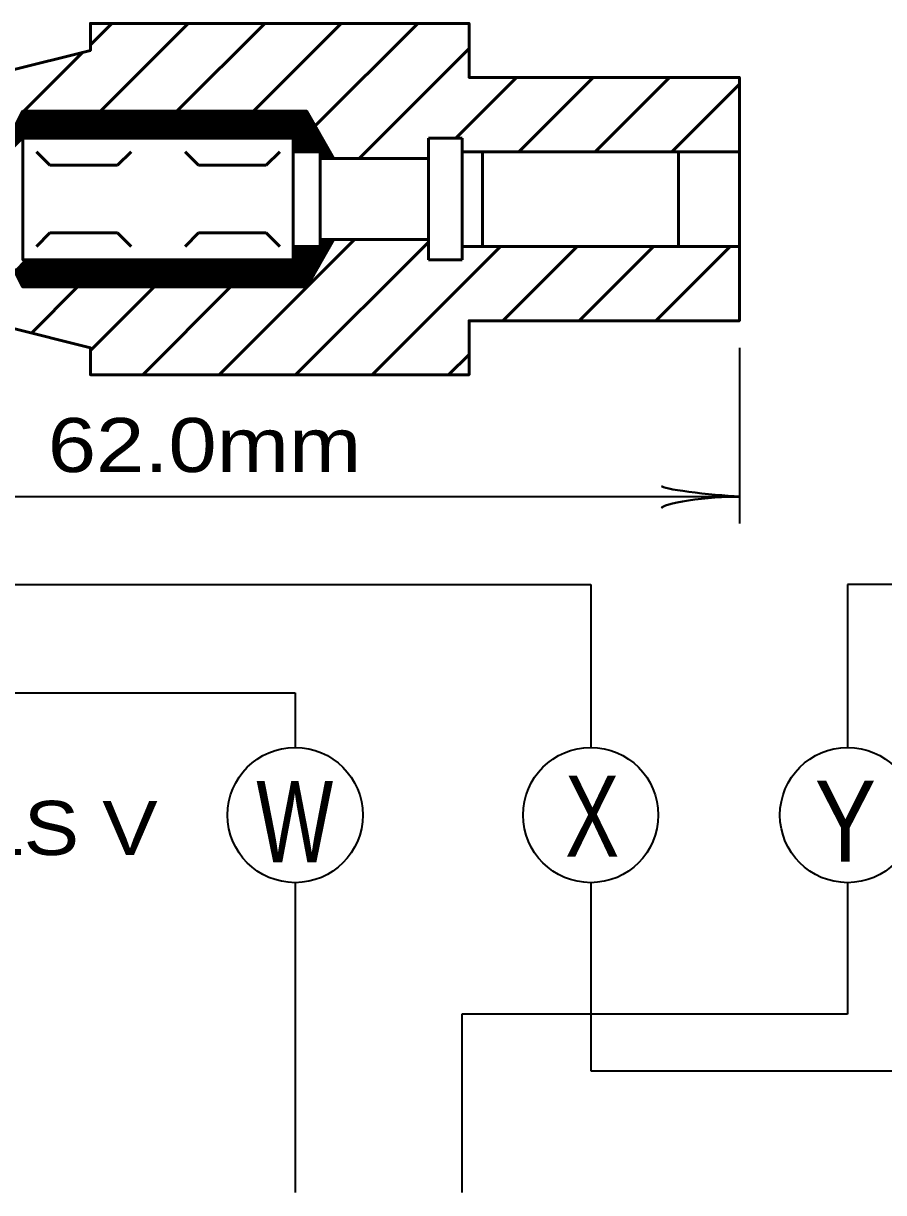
# Model space of a CAD drawing. Extents: x -32 to 824, y -6 to 538.
# Drawn here: x 382.7 to 420.9, y 130.6 to 182.5 of the extents above; entities that cross this region are included whole.
import ezdxf

# ---------------------------------------------------------------- set-up
doc = ezdxf.new("R2010")
doc.units = 0
doc.header["$LTSCALE"] = 1.1
doc.layers.add('1', color=7, linetype='Continuous', lineweight=53)

msp = doc.modelspace()

# ---------------------------------------------------------------- linework, layer by layer
at = {"layer": '1'}
for p, q in [((385.679, 181.513), (386.627, 182.462)), ((386.122, 178.562), (390.022, 182.462)), ((389.516, 178.562), (393.416, 182.462)), ((392.91, 178.562), (396.81, 182.462)), ((395.652, 177.909), (400.204, 182.462)), ((382.727, 178.562), (385.344, 181.178)), ((397.598, 176.462), (402.479, 181.343)), ((401.892, 177.362), (404.592, 180.062)), ((404.686, 176.762), (407.986, 180.062)), ((408.08, 176.762), (411.38, 180.062)), ((411.474, 176.762), (414.479, 179.766)), ((379.88, 175.112), (383.33, 178.562)), ((380.05, 175.112), (383.5, 178.562)), ((380.219, 175.112), (383.669, 178.562)), ((380.389, 175.112), (383.839, 178.562)), ((382.198, 177.599), (383.16, 178.562)), ((382.367, 177.939), (382.99, 178.562)), ((382.537, 178.278), (382.821, 178.562)), ((382.809, 177.362), (384.009, 178.562)), ((382.978, 177.362), (384.178, 178.562)), ((383.148, 177.362), (384.348, 178.562)), ((383.318, 177.362), (384.518, 178.562)), ((383.487, 177.362), (384.687, 178.562)), ((383.657, 177.362), (384.857, 178.562)), ((383.827, 177.362), (385.027, 178.562)), ((383.997, 177.362), (385.197, 178.562)), ((384.166, 177.362), (385.366, 178.562)), ((384.336, 177.362), (385.536, 178.562)), ((384.506, 177.362), (385.706, 178.562)), ((384.675, 177.362), (385.875, 178.562)), ((384.845, 177.362), (386.045, 178.562)), ((385.015, 177.362), (386.215, 178.562)), ((385.185, 177.362), (386.385, 178.562)), ((385.354, 177.362), (386.554, 178.562)), ((385.524, 177.362), (386.724, 178.562)), ((385.694, 177.362), (386.894, 178.562)), ((385.863, 177.362), (387.063, 178.562)), ((386.033, 177.362), (387.233, 178.562)), ((386.203, 177.362), (387.403, 178.562)), ((386.372, 177.362), (387.572, 178.562)), ((386.542, 177.362), (387.742, 178.562)), ((386.712, 177.362), (387.912, 178.562)), ((386.882, 177.362), (388.082, 178.562)), ((387.051, 177.362), (388.251, 178.562)), ((387.221, 177.362), (388.421, 178.562)), ((387.391, 177.362), (388.591, 178.562)), ((387.56, 177.362), (388.76, 178.562)), ((387.73, 177.362), (388.93, 178.562)), ((387.9, 177.362), (389.1, 178.562)), ((388.07, 177.362), (389.269, 178.562)), ((388.239, 177.362), (389.439, 178.562)), ((388.409, 177.362), (389.609, 178.562)), ((388.579, 177.362), (389.779, 178.562)), ((388.748, 177.362), (389.948, 178.562)), ((388.918, 177.362), (390.118, 178.562)), ((389.088, 177.362), (390.288, 178.562)), ((389.257, 177.362), (390.457, 178.562)), ((389.427, 177.362), (390.627, 178.562)), ((389.597, 177.362), (390.797, 178.562)), ((389.767, 177.362), (390.966, 178.562)), ((389.936, 177.362), (391.136, 178.562)), ((390.106, 177.362), (391.306, 178.562)), ((390.276, 177.362), (391.476, 178.562)), ((390.445, 177.362), (391.645, 178.562)), ((390.615, 177.362), (391.815, 178.562)), ((390.785, 177.362), (391.985, 178.562)), ((390.954, 177.362), (392.155, 178.562)), ((391.124, 177.362), (392.324, 178.562)), ((391.294, 177.362), (392.494, 178.562)), ((391.464, 177.362), (392.664, 178.562)), ((391.633, 177.362), (392.833, 178.562)), ((391.803, 177.362), (393.003, 178.562)), ((391.973, 177.362), (393.173, 178.562)), ((392.142, 177.362), (393.342, 178.562)), ((392.312, 177.362), (393.512, 178.562)), ((392.482, 177.362), (393.682, 178.562)), ((392.651, 177.362), (393.852, 178.562)), ((392.821, 177.362), (394.021, 178.562)), ((392.991, 177.362), (394.191, 178.562)), ((393.161, 177.362), (394.361, 178.562)), ((393.33, 177.362), (394.53, 178.562)), ((393.5, 177.362), (394.7, 178.562)), ((393.67, 177.362), (394.87, 178.562)), ((393.84, 177.362), (395.04, 178.562)), ((394.009, 177.362), (395.209, 178.562)), ((394.179, 177.362), (395.315, 178.498)), ((394.349, 177.362), (395.377, 178.39)), ((394.518, 177.362), (395.439, 178.282)), ((394.679, 177.353), (395.5, 178.174)), ((394.679, 177.183), (395.562, 178.066)), ((394.679, 177.013), (395.624, 177.958)), ((394.679, 176.843), (395.686, 177.85)), ((394.767, 176.762), (395.747, 177.742)), ((394.937, 176.762), (395.809, 177.634)), ((395.106, 176.762), (395.871, 177.526)), ((395.276, 176.762), (395.932, 177.418)), ((395.446, 176.762), (395.994, 177.31)), ((395.615, 176.762), (396.056, 177.202)), ((395.785, 176.762), (396.118, 177.094)), ((395.879, 176.686), (396.179, 176.986)), ((400.679, 177.362), (400.679, 171.962)), ((400.679, 177.362), (402.179, 177.362)), ((402.179, 177.362), (402.179, 171.962)), ((383.879, 176.162), (383.279, 176.762)), ((386.879, 176.162), (387.479, 176.762)), ((390.479, 176.162), (389.879, 176.762)), ((393.479, 176.162), (394.079, 176.762)), ((394.679, 176.762), (394.679, 172.562)), ((395.879, 176.516), (396.241, 176.878)), ((395.879, 176.462), (395.879, 172.862)), ((395.994, 176.462), (396.303, 176.77)), ((396.164, 176.462), (396.364, 176.662)), ((396.334, 176.462), (396.426, 176.554)), ((396.479, 176.462), (400.679, 176.462)), ((402.179, 176.762), (414.479, 176.762)), ((403.079, 176.762), (403.079, 172.562)), ((383.879, 176.162), (386.879, 176.162)), ((390.479, 176.162), (393.479, 176.162)), ((383.879, 173.162), (383.279, 172.562)), ((383.879, 173.162), (386.879, 173.162)), ((386.879, 173.162), (387.479, 172.562)), ((390.479, 173.162), (389.879, 172.562)), ((390.479, 173.162), (393.479, 173.162)), ((391.392, 166.862), (397.392, 172.862)), ((393.479, 173.162), (394.079, 172.562)), ((394.197, 170.762), (396.297, 172.862)), ((394.367, 170.762), (396.467, 172.862)), ((395.879, 172.782), (395.958, 172.862)), ((395.879, 172.613), (396.128, 172.862)), ((396.479, 172.862), (400.679, 172.862)), ((393.519, 170.762), (395.319, 172.562)), ((393.688, 170.762), (395.488, 172.562)), ((393.858, 170.762), (395.658, 172.562)), ((394.028, 170.762), (395.828, 172.562)), ((394.537, 170.762), (396.268, 172.493)), ((394.679, 172.431), (394.81, 172.562)), ((394.679, 172.261), (394.979, 172.562)), ((394.679, 172.092), (395.149, 172.562)), ((394.786, 166.862), (400.679, 172.754)), ((398.18, 166.862), (403.88, 172.562)), ((402.179, 172.562), (414.479, 172.562)), ((403.974, 169.262), (407.274, 172.562)), ((407.369, 169.262), (410.669, 172.562)), ((410.763, 169.262), (414.063, 172.562)), ((382.332, 171.455), (382.839, 171.962)), ((382.389, 171.342), (383.009, 171.962)), ((382.446, 171.228), (383.179, 171.962)), ((382.502, 171.115), (383.348, 171.962)), ((382.559, 171.002), (383.518, 171.962)), ((382.615, 170.889), (383.688, 171.962)), ((382.672, 170.776), (383.857, 171.962)), ((382.827, 170.762), (384.027, 171.962)), ((382.997, 170.762), (384.197, 171.962)), ((383.167, 170.762), (384.367, 171.962)), ((383.336, 170.762), (384.536, 171.962)), ((383.506, 170.762), (384.706, 171.962)), ((383.676, 170.762), (384.876, 171.962)), ((383.845, 170.762), (385.045, 171.962)), ((384.015, 170.762), (385.215, 171.962)), ((384.185, 170.762), (385.385, 171.962)), ((384.355, 170.762), (385.555, 171.962)), ((384.524, 170.762), (385.724, 171.962)), ((384.694, 170.762), (385.894, 171.962)), ((384.864, 170.762), (386.064, 171.962)), ((385.033, 170.762), (386.233, 171.962)), ((385.203, 170.762), (386.403, 171.962)), ((385.373, 170.762), (386.573, 171.962)), ((385.542, 170.762), (386.742, 171.962)), ((385.712, 170.762), (386.912, 171.962)), ((385.882, 170.762), (387.082, 171.962)), ((386.052, 170.762), (387.252, 171.962)), ((386.221, 170.762), (387.421, 171.962)), ((386.391, 170.762), (387.591, 171.962)), ((386.561, 170.762), (387.761, 171.962)), ((386.73, 170.762), (387.93, 171.962)), ((386.9, 170.762), (388.1, 171.962)), ((387.07, 170.762), (388.27, 171.962)), ((387.24, 170.762), (388.44, 171.962)), ((387.409, 170.762), (388.609, 171.962)), ((387.579, 170.762), (388.779, 171.962)), ((387.749, 170.762), (388.949, 171.962)), ((387.918, 170.762), (389.118, 171.962)), ((388.088, 170.762), (389.288, 171.962)), ((388.258, 170.762), (389.458, 171.962)), ((388.427, 170.762), (389.627, 171.962)), ((388.597, 170.762), (389.797, 171.962)), ((388.767, 170.762), (389.967, 171.962)), ((388.937, 170.762), (390.137, 171.962)), ((389.106, 170.762), (390.306, 171.962)), ((389.276, 170.762), (390.476, 171.962)), ((389.446, 170.762), (390.646, 171.962)), ((389.615, 170.762), (390.815, 171.962)), ((389.785, 170.762), (390.985, 171.962)), ((389.955, 170.762), (391.155, 171.962)), ((390.125, 170.762), (391.325, 171.962)), ((390.294, 170.762), (391.494, 171.962)), ((390.464, 170.762), (391.664, 171.962)), ((390.634, 170.762), (391.834, 171.962)), ((390.803, 170.762), (392.003, 171.962)), ((390.973, 170.762), (392.173, 171.962)), ((391.143, 170.762), (392.343, 171.962)), ((391.312, 170.762), (392.512, 171.962)), ((391.482, 170.762), (392.682, 171.962)), ((391.652, 170.762), (392.852, 171.962)), ((391.822, 170.762), (393.022, 171.962)), ((391.991, 170.762), (393.191, 171.962)), ((392.161, 170.762), (393.361, 171.962)), ((392.331, 170.762), (393.531, 171.962)), ((392.5, 170.762), (393.7, 171.962)), ((392.67, 170.762), (393.87, 171.962)), ((392.84, 170.762), (394.04, 171.962)), ((393.01, 170.762), (394.209, 171.962)), ((393.179, 170.762), (394.379, 171.962)), ((393.349, 170.762), (394.549, 171.962)), ((394.707, 170.762), (396.042, 172.097)), ((400.679, 171.962), (402.179, 171.962)), ((394.876, 170.762), (395.816, 171.701)), ((395.046, 170.762), (395.59, 171.305)), ((383.064, 168.715), (385.11, 170.762)), ((385.679, 167.937), (388.504, 170.762)), ((387.998, 166.862), (391.898, 170.762)), ((395.216, 170.762), (395.363, 170.909)), ((402.479, 169.262), (414.479, 169.262)), ((401.574, 166.862), (402.479, 167.766)), ((402.479, 166.862), (385.679, 166.862))]:
    msp.add_line(p, q, dxfattribs=at)
at = {"layer": '1', "lineweight": 35}
for p, q in [((414.479, 168.062), (414.479, 160.262)), ((367.679, 161.462), (414.479, 161.462)), ((343.679, 157.562), (407.879, 157.562)), ((407.879, 157.562), (407.879, 150.32)), ((472.079, 157.562), (419.279, 157.562)), ((419.279, 157.562), (419.279, 150.32)), ((358.679, 152.752), (394.762, 152.752)), ((394.762, 152.752), (394.762, 152.752)), ((394.762, 152.752), (394.762, 150.32)), ((394.762, 144.32), (394.762, 130.562)), ((407.879, 144.32), (407.879, 135.962)), ((419.279, 144.32), (419.279, 138.481)), ((402.165, 138.481), (402.165, 130.562)), ((419.279, 138.481), (402.165, 138.481)), ((402.165, 138.481), (402.165, 133.081)), ((407.879, 135.962), (463.649, 135.962))]:
    msp.add_line(p, q, dxfattribs=at)
at = {"layer": '1'}
for points in [[(378.479, 179.462), (385.679, 181.262), (385.679, 182.462), (402.479, 182.462), (402.479, 180.062), (414.479, 180.062), (414.479, 172.562), (414.479, 169.262), (402.479, 169.262), (402.479, 166.862), (385.679, 166.862), (385.679, 168.062), (378.479, 169.862), (367.679, 169.862), (367.679, 171.962)], [(358.679, 177.362), (382.079, 177.362), (382.679, 178.562), (395.279, 178.562), (396.479, 176.462), (395.879, 176.462), (395.879, 176.762), (394.679, 176.762), (394.679, 177.362), (382.679, 177.362), (382.679, 171.962), (394.679, 171.962), (394.679, 172.562), (395.879, 172.562), (395.879, 172.862), (396.479, 172.862), (395.279, 170.762), (382.679, 170.762), (382.079, 171.962), (352.679, 171.962)]]:
    msp.add_lwpolyline(points, dxfattribs=at)
for points in [[(352.679, 171.962), (352.679, 177.362), (382.079, 177.362), (382.679, 178.562), (395.279, 178.562), (396.479, 176.462), (395.879, 176.462), (395.879, 176.762), (394.679, 176.762), (394.679, 177.362), (382.679, 177.362), (382.679, 171.962), (394.679, 171.962), (394.679, 172.562), (395.879, 172.562), (395.879, 172.862), (396.479, 172.862), (395.279, 170.762), (382.679, 170.762), (382.079, 171.962)], [(352.679, 171.962), (352.679, 177.362), (382.079, 177.362), (382.679, 178.562), (395.279, 178.562), (396.479, 176.462), (395.879, 176.462), (395.879, 176.762), (394.679, 176.762), (394.679, 177.362), (382.679, 177.362), (382.679, 171.962), (394.679, 171.962), (394.679, 172.562), (395.879, 172.562), (395.879, 172.862), (396.479, 172.862), (395.279, 170.762), (382.679, 170.762), (382.079, 171.962)], [(411.779, 172.562), (411.779, 176.762), (414.479, 176.762), (414.479, 172.562)]]:
    msp.add_lwpolyline(points, close=True, dxfattribs=at)
at = {"layer": '1', "lineweight": 35}
for centre in [(394.762, 147.32), (407.879, 147.32), (419.279, 147.32)]:
    msp.add_circle(centre, 3, dxfattribs=at)
at = {"layer": '1', "lineweight": 40}
for centre, major_axis, ratio, start_param, end_param in [((413.169, 161.13), (2.143, 0.187), 0.122415, 0.896353, 3.141593), ((413.169, 161.13), (2.143, 0.187), 0.122415, 0.896353, 3.141593), ((413.134, 161.716), (2.108, -0.211), 0.07063, 3.140715, 5.41811), ((413.134, 161.716), (2.108, -0.211), 0.07063, 3.140715, 5.41811)]:
    msp.add_ellipse(centre, major_axis=major_axis, ratio=ratio, start_param=start_param, end_param=end_param, dxfattribs=at)

# ---------------------------------------------------------------- texts
at = {"layer": '1'}
for s, height, width, p in [('62.0mm', 2.4, 1.2, (383.786, 162.546)), ('X', 3.6, 0.75, (406.74, 145.468)), ('W', 3.6, 0.75, (393.042, 145.227)), ('Y', 3.6, 0.85, (417.819, 145.254)), ('IDENTIFYING SYMBOLS V', 2.4, 1.15, (342.931, 145.549))]:
    msp.add_text(s, height=height, dxfattribs=dict(at, width=width)).set_placement(p)

doc.saveas('drawing.dxf')
